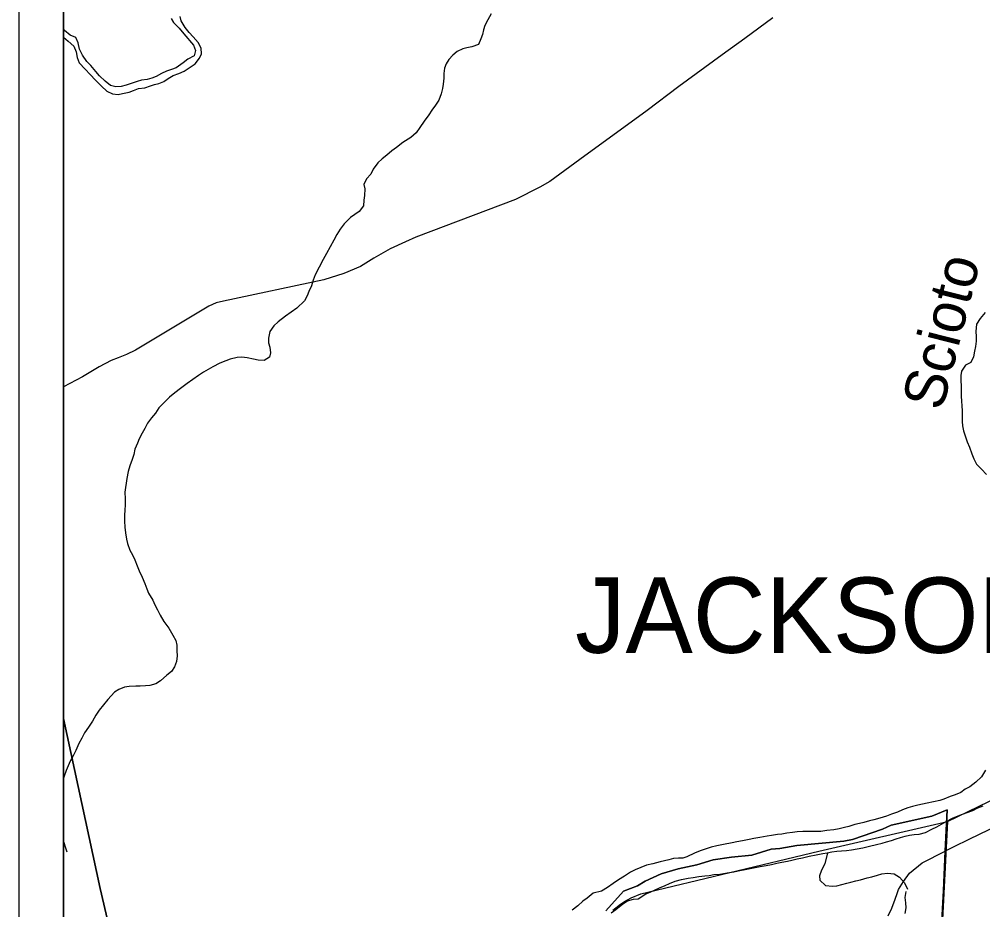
# Model space of a CAD drawing. Extents: x 0 to 34, y 0 to 22.
# Drawn here: x 23.917 to 26.095, y 16.768 to 18.782 of the extents above; entities that cross this region are included whole.
import ezdxf

# ---------------------------------------------------------------- set-up
doc = ezdxf.new("R2010")
doc.units = 0
for name, color, linetype in [('GM_X_County', 7, 'Continuous'), ('GM_X_County_Road', 7, 'Continuous'), ('GM_X_Major_River', 7, 'Continuous'), ('GM_X_Major_River_Text', 7, 'Continuous'), ('GM_X_Minor_River', 7, 'Continuous'), ('GM_X_Section', 7, 'Continuous'), ('GM_X_State_Route', 7, 'Continuous'), ('GM_X_Township', 7, 'Continuous'), ('GM_X_Township_Text', 7, 'Continuous'), ('SH_Data', 7, 'Continuous')]:
    doc.layers.add(name, color=color, linetype=linetype)

msp = doc.modelspace()

# ---------------------------------------------------------------- linework, layer by layer
at = {"layer": 'GM_X_County'}
msp.add_lwpolyline([(24.0167, 20.4902), (24.0167, 14.1), (30.8167, 14.1), (30.8167, 19.9966)], dxfattribs=at)
at = {"layer": 'GM_X_County_Road'}
for points in [[(26.029, 16.9104), (26.066, 16.9284), (26.1704, 16.9793)], [(26.011, 16.9016), (26.029, 16.9104)], [(25.9016, 16.8052), (25.9024, 16.8075), (25.9049, 16.8141), (25.9156, 16.8326), (25.9297, 16.8512), (25.9584, 16.8748), (26.0099, 16.901), (26.011, 16.9016)], [(25.8811, 16.7546), (25.8895, 16.7721), (25.8968, 16.7925), (25.9016, 16.8052)]]:
    msp.add_lwpolyline(points, dxfattribs=at)
at = {"layer": 'GM_X_Major_River'}
for points in [[(26.1007, 18.1189), (26.0892, 18.1054), (26.0808, 18.0926), (26.0794, 18.0759), (26.0801, 18.0649), (26.08, 18.0539), (26.0787, 18.0418), (26.0767, 18.0316), (26.0739, 18.0188), (26.0677, 18.0059), (26.0559, 17.9996), (26.0471, 17.9861), (26.0455, 17.9762), (26.0453, 17.9641), (26.046, 17.9539), (26.0462, 17.9417), (26.0465, 17.93), (26.0471, 17.9186), (26.0478, 17.908), (26.0488, 17.897), (26.0483, 17.8863), (26.0485, 17.8727), (26.0492, 17.8625), (26.0517, 17.8514), (26.0557, 17.8377), (26.0601, 17.8263), (26.0649, 17.8145), (26.07, 17.7997), (26.0745, 17.7879), (26.0808, 17.776), (26.0924, 17.7645), (26.1036, 17.7526)], [(26.101, 17.0843), (26.0921, 17.0692), (26.0795, 17.0568), (26.0658, 17.0467), (26.0555, 17.0408), (26.0456, 17.0337), (26.0323, 17.0285), (26.0216, 17.0241), (26.0072, 17.0186), (25.9977, 17.0157), (25.9833, 17.0124), (25.9693, 17.0091), (25.959, 17.0074), (25.9481, 17.0052), (25.9359, 17.0016), (25.9253, 16.9986), (25.9135, 16.9942), (25.9021, 16.989), (25.8888, 16.9843), (25.8771, 16.9802), (25.8623, 16.9758), (25.849, 16.9718), (25.8391, 16.9693), (25.8258, 16.966), (25.8164, 16.9635), (25.8061, 16.9609), (25.7925, 16.9569), (25.7826, 16.954), (25.7705, 16.9515), (25.7583, 16.9493), (25.7428, 16.9472), (25.7288, 16.9451), (25.7167, 16.9452), (25.7, 16.9451), (25.6883, 16.9456), (25.6754, 16.9446), (25.6652, 16.9432), (25.6523, 16.9414), (25.641, 16.9396), (25.6307, 16.9382), (25.6171, 16.9365), (25.6073, 16.9347), (25.591, 16.9319), (25.5777, 16.9297), (25.5667, 16.9272), (25.5515, 16.9243), (25.539, 16.9222), (25.5288, 16.92), (25.5091, 16.9161), (25.4939, 16.9129), (25.481, 16.9096), (25.4677, 16.9056), (25.4564, 16.9015), (25.4434, 16.896), (25.4263, 16.8878), (25.4168, 16.8853), (25.407, 16.885), (25.3956, 16.884), (25.3854, 16.8815), (25.3752, 16.8793), (25.3653, 16.8768), (25.349, 16.8724), (25.335, 16.8688), (25.3221, 16.864), (25.3095, 16.8588), (25.2989, 16.8532), (25.2852, 16.8443), (25.2718, 16.8361), (25.2593, 16.8279), (25.2463, 16.8189), (25.2333, 16.8104)], [(25.3335, 16.8043), (25.343, 16.8084), (25.354, 16.8132), (25.3639, 16.8176), (25.3772, 16.8232), (25.3871, 16.828), (25.3996, 16.8328), (25.4137, 16.8364), (25.4292, 16.8396), (25.4406, 16.8414), (25.4531, 16.8432), (25.4663, 16.8449), (25.4762, 16.8459), (25.4868, 16.8477), (25.5004, 16.8487), (25.5175, 16.8516), (25.5323, 16.8544), (25.5459, 16.8573), (25.5577, 16.8594), (25.5694, 16.862), (25.5804, 16.8641), (25.5921, 16.8663), (25.605, 16.8684), (25.6172, 16.8709), (25.6297, 16.8734), (25.641, 16.876), (25.6535, 16.8781), (25.663, 16.8803), (25.6752, 16.8832), (25.6873, 16.8857), (25.7025, 16.8893), (25.7184, 16.8925), (25.7332, 16.8954), (25.743, 16.8972), (25.7536, 16.899), (25.765, 16.9007), (25.7756, 16.9017), (25.7866, 16.9024), (25.7979, 16.9038), (25.8108, 16.9059), (25.8241, 16.9084), (25.8393, 16.912), (25.8548, 16.9156), (25.8673, 16.9189), (25.8776, 16.9222), (25.8886, 16.9251), (25.8996, 16.9288), (25.9094, 16.9321), (25.9197, 16.9346), (25.9292, 16.9368), (25.9402, 16.9382), (25.9515, 16.9396), (25.9652, 16.9428), (25.9796, 16.9503), (25.991, 16.9558), (26.0017, 16.9618), (26.0123, 16.9681), (26.0264, 16.9755), (26.0393, 16.9807), (26.0492, 16.9844), (26.0595, 16.988), (26.0727, 16.9928), (26.0842, 16.9991), (26.0963, 17.0036)], [(25.2333, 16.8104), (25.2144, 16.8058), (25.2007, 16.7949), (25.1911, 16.7875), (25.1796, 16.7774), (25.1667, 16.7673)], [(25.2548, 16.7613), (25.2655, 16.7692), (25.2811, 16.7819), (25.2918, 16.7886), (25.3055, 16.7926), (25.3157, 16.7928), (25.3335, 16.8043)]]:
    msp.add_lwpolyline(points, dxfattribs=at)
at = {"layer": 'GM_X_Minor_River'}
for points in [[(24.0766, 18.6573), (24.0893, 18.6443), (24.1024, 18.6312), (24.1148, 18.6197), (24.1272, 18.6135), (24.1401, 18.6118), (24.15, 18.6143), (24.1652, 18.6172), (24.1751, 18.6213), (24.1865, 18.6253), (24.2005, 18.6274), (24.2131, 18.6318), (24.2226, 18.6344), (24.2325, 18.6369), (24.2435, 18.6414), (24.2535, 18.6485), (24.2645, 18.6548), (24.2771, 18.6599), (24.2893, 18.6651), (24.3011, 18.6722), (24.3141, 18.6812), (24.3245, 18.6939), (24.3284, 18.7038), (24.3281, 18.7167), (24.3215, 18.7297), (24.3095, 18.7423), (24.3009, 18.7523), (24.2915, 18.7638), (24.283, 18.7783), (24.2804, 18.7882)], [(24.2599, 18.7843), (24.2655, 18.7747), (24.2779, 18.762), (24.2887, 18.749), (24.3104, 18.7237), (24.3152, 18.7119), (24.3124, 18.6998), (24.2979, 18.6916), (24.2876, 18.6834), (24.2715, 18.6722), (24.2609, 18.6689), (24.2498, 18.6648), (24.2384, 18.6593), (24.2262, 18.6529), (24.2167, 18.6489), (24.2061, 18.6463), (24.1931, 18.6442), (24.1829, 18.6417), (24.1699, 18.6373), (24.1582, 18.6332), (24.1467, 18.6303), (24.135, 18.6297), (24.1229, 18.6325), (24.1105, 18.6421), (24.0981, 18.6544)], [(24.9839, 18.7946), (24.9758, 18.7806), (24.9696, 18.7682), (24.966, 18.7583), (24.9637, 18.7477), (24.9601, 18.7379), (24.9547, 18.7251), (24.9398, 18.7199), (24.9288, 18.7174), (24.9193, 18.7152), (24.9067, 18.7093), (24.8968, 18.7011), (24.888, 18.6913), (24.8822, 18.6811), (24.8783, 18.6713), (24.8766, 18.6595), (24.8765, 18.6493), (24.8748, 18.6356), (24.8736, 18.6258), (24.8704, 18.6133), (24.8649, 18.5989), (24.8576, 18.5876), (24.8495, 18.5763), (24.8426, 18.5662), (24.8322, 18.5519), (24.8222, 18.5376), (24.8137, 18.5255), (24.8018, 18.5147), (24.7839, 18.5035), (24.7693, 18.4919), (24.759, 18.4844), (24.7475, 18.4747), (24.7372, 18.4664), (24.7276, 18.4578), (24.7169, 18.4435), (24.7118, 18.4318), (24.7015, 18.4217), (24.6956, 18.4088), (24.6982, 18.3986), (24.6972, 18.3834), (24.696, 18.3728), (24.6947, 18.3603), (24.6851, 18.3471), (24.6755, 18.3408), (24.6656, 18.3337), (24.6514, 18.3198), (24.6422, 18.3077), (24.6345, 18.2957), (24.6275, 18.2829), (24.6194, 18.2678), (24.6112, 18.2523), (24.6039, 18.2387), (24.586, 18.204), (24.5814, 18.1919), (24.577, 18.1794), (24.5716, 18.1666), (24.5677, 18.1564), (24.5615, 18.1451), (24.5439, 18.129), (24.5316, 18.1196), (24.5183, 18.1107), (24.5018, 18.098), (24.4919, 18.089), (24.483, 18.0758), (24.4798, 18.061), (24.4805, 18.0508), (24.483, 18.0405), (24.4847, 18.0279), (24.4824, 18.0181), (24.4705, 18.0106), (24.4565, 18.0116), (24.4463, 18.0136), (24.4316, 18.0168), (24.4195, 18.0181)], [(24.0981, 18.6544), (24.0899, 18.6644), (24.0787, 18.6774), (24.0693, 18.687), (24.06, 18.7012), (24.053, 18.7145), (24.0501, 18.729), (24.0442, 18.7408), (24.0321, 18.7466), (24.019, 18.7567), (24.0167, 18.7602)], [(24.0167, 18.7416), (24.0274, 18.733), (24.0398, 18.7215), (24.0453, 18.7089), (24.0475, 18.696), (24.0519, 18.6838), (24.0653, 18.6696), (24.0766, 18.6573)], [(24.4195, 18.0181), (24.4096, 18.0174), (24.3936, 18.0138), (24.3837, 18.0097), (24.3704, 18.0042), (24.3544, 17.9964), (24.3441, 17.9905), (24.3334, 17.9838), (24.322, 17.9763), (24.296, 17.9584), (24.2815, 17.9475), (24.2681, 17.9374), (24.2562, 17.9273), (24.2424, 17.9138), (24.2324, 17.9033), (24.2247, 17.8913), (24.2155, 17.8807), (24.2067, 17.8691), (24.2005, 17.8566), (24.1947, 17.8464), (24.1881, 17.8336), (24.1838, 17.8234), (24.1783, 17.8102), (24.1755, 17.7981), (24.1716, 17.7864), (24.1665, 17.7724), (24.163, 17.7591), (24.1598, 17.7436), (24.1581, 17.733), (24.1569, 17.7235), (24.1556, 17.7125), (24.1562, 17.6977), (24.156, 17.6841), (24.1552, 17.6723), (24.1543, 17.661), (24.1545, 17.6473), (24.1551, 17.6336), (24.1565, 17.6207), (24.159, 17.6066), (24.1615, 17.5964), (24.167, 17.5819), (24.1726, 17.5712), (24.1777, 17.5594), (24.1829, 17.546), (24.1877, 17.5346), (24.1944, 17.5204), (24.2003, 17.506), (24.205, 17.4941), (24.2091, 17.4846), (24.2188, 17.4682), (24.2232, 17.4579), (24.2295, 17.4464), (24.2351, 17.4342), (24.2436, 17.4201), (24.2548, 17.4051), (24.2641, 17.3895), (24.2704, 17.3769), (24.2726, 17.367), (24.2732, 17.3541), (24.2734, 17.3427), (24.2721, 17.3298), (24.2678, 17.3177), (24.2609, 17.3075), (24.2506, 17.2989), (24.2356, 17.2858), (24.2253, 17.2795), (24.212, 17.2755), (24.2018, 17.2744), (24.1897, 17.2742), (24.1802, 17.2743), (24.165, 17.2733), (24.1548, 17.2716), (24.1418, 17.2664), (24.1323, 17.2604), (24.1169, 17.2439), (24.1069, 17.2315), (24.0973, 17.2195), (24.0896, 17.2082), (24.0823, 17.195), (24.073, 17.181), (24.0645, 17.1682), (24.058, 17.1562), (24.0517, 17.1441), (24.0444, 17.1286), (24.0382, 17.1165), (24.0316, 17.1041), (24.0269, 17.0935), (24.0226, 17.083), (24.0172, 17.0682), (24.0167, 17.066)], [(24.0167, 16.9228), (24.0174, 16.9202), (24.0203, 16.9107)], [(24.0203, 16.9107), (24.0243, 16.8996)], [(25.7437, 16.8973), (25.7381, 16.872), (25.7303, 16.8577), (25.726, 16.8448), (25.7263, 16.8353), (25.7394, 16.823), (25.7553, 16.8217), (25.7648, 16.8227), (25.7766, 16.8256), (25.7876, 16.8285), (25.7971, 16.8311), (25.8081, 16.8336), (25.8187, 16.8362), (25.8336, 16.8402), (25.8442, 16.8431), (25.8568, 16.8467), (25.867, 16.8496), (25.8799, 16.851), (25.8947, 16.8497), (25.9067, 16.8424), (25.9179, 16.8289), (25.925, 16.8152)], [(25.9211, 16.8094), (25.9189, 16.7962), (25.9202, 16.784), (25.9211, 16.773), (25.919, 16.7601)]]:
    msp.add_lwpolyline(points, dxfattribs=at)
at = {"layer": 'GM_X_Section'}
msp.add_lwpolyline([(26.2538, 17.2713), (27.0604, 17.2208), (27.0998, 17.2184), (27.0114, 16.2186), (25.9802, 16.2732), (26.0152, 16.9679), (26.1318, 17.0242)], close=True, dxfattribs=at)
msp.add_lwpolyline([(25.2583, 16.7675), (25.2762, 16.7807), (25.2853, 16.7867), (25.2918, 16.7908), (25.3001, 16.7954), (25.3216, 16.8044), (25.7246, 16.9007), (26.0152, 16.9679), (25.9802, 16.2732)], dxfattribs=at)
at = {"layer": 'GM_X_State_Route'}
msp.add_lwpolyline([(25.6207, 18.7858), (25.5574, 18.7385), (25.5059, 18.7015), (25.4082, 18.6302), (25.3366, 18.5761), (25.1839, 18.4648), (25.1161, 18.4152), (25.0938, 18.4026), (25.0388, 18.3748), (24.8132, 18.2894), (24.7897, 18.2787), (24.7556, 18.2631), (24.7181, 18.2421), (24.6881, 18.2234), (24.6506, 18.207), (24.6051, 18.1932), (24.3786, 18.1447), (24.3619, 18.1412), (24.3456, 18.1332), (24.1796, 18.0336), (24.1588, 18.0237), (24.1402, 18.0168), (24.1243, 18.0103), (24.0974, 17.9962), (24.06, 17.9737), (24.0167, 17.9512)], dxfattribs=at)
at = {"layer": 'GM_X_Township'}
for p, q in [((24.0167, 20.4902), (24.0167, 17.2008)), ((24.0167, 17.2008), (24.0167, 16.2296))]:
    msp.add_line(p, q, dxfattribs=at)
for points in [[(24.0167, 17.2008), (24.0999, 16.8163), (24.2144, 16.3267)], [(24.0167, 16.2296), (24.1434, 16.2932), (24.2144, 16.3267), (24.0999, 16.8163), (24.0167, 17.2008)], [(25.243, 16.7662), (25.2825, 16.8107), (25.3145, 16.8226), (25.332, 16.8331), (25.3677, 16.8495), (25.406, 16.861), (25.4488, 16.8701), (25.4856, 16.8809), (25.5269, 16.8874), (25.5727, 16.8919), (25.617, 16.9053), (25.636, 16.907), (25.675, 16.9139), (25.7806, 16.9233), (25.8003, 16.9274), (25.8682, 16.9503), (25.8883, 16.9593), (25.98, 16.9802), (26.0149, 16.994), (26.0099, 16.901), (26.0061, 16.8119), (25.9768, 16.2716)], [(25.9768, 16.2716), (26.0061, 16.8119), (26.0099, 16.901), (26.0149, 16.994), (25.98, 16.9802), (25.8883, 16.9593), (25.8682, 16.9503), (25.8003, 16.9274), (25.7806, 16.9233), (25.675, 16.9139), (25.636, 16.907), (25.617, 16.9053), (25.5727, 16.8919), (25.5269, 16.8874), (25.4856, 16.8809), (25.4488, 16.8701), (25.406, 16.861), (25.3677, 16.8495), (25.332, 16.8331), (25.3145, 16.8226), (25.2825, 16.8107), (25.243, 16.7662)]]:
    msp.add_lwpolyline(points, dxfattribs=at)
at = {"layer": 'SH_Data'}
for points in [[(23.9167, 21), (30.9167, 21), (30.9167, 14), (23.9167, 14)], [(24.0167, 20.9), (30.8167, 20.9), (30.8167, 14.1), (24.0167, 14.1)]]:
    msp.add_lwpolyline(points, close=True, dxfattribs=at)

# ---------------------------------------------------------------- texts
at = {"layer": 'GM_X_Major_River_Text'}
msp.add_text('Scioto', height=0.09471, rotation=75.7669, dxfattribs=at).set_placement((26.0032, 17.8943))
at = {"layer": 'GM_X_Township_Text'}
msp.add_text('JACKSON', height=0.17045, rotation=0, dxfattribs=at).set_placement((25.1734, 17.3493))

doc.saveas('drawing.dxf')
